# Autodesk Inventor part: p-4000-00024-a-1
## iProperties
Shininess: 64.0
Length Units: 11269
Angle Units: 11279
Time Units: 11290
Mass Units: 11283
Length Display Precision: 3
Angle Display Precision: 2
Compacted: True
Part Number: p-4000-00024-a-1
Document SubType Name: Sheet Metal
Created: 2004-09
Material: Stahl (schweißbar)
Density: 0.0
Volumn: 0.0
Area: 0.0
PropertySet Name: Model Information
Control State: 0
Master: False
Checked Out: False
Author: M.S
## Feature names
1. Bohrung1 [Hole]
2. Bohrung2 [Hole]
3. Platte1
4. ExtrusionAbwicklung1
5. Ausklinkung1
